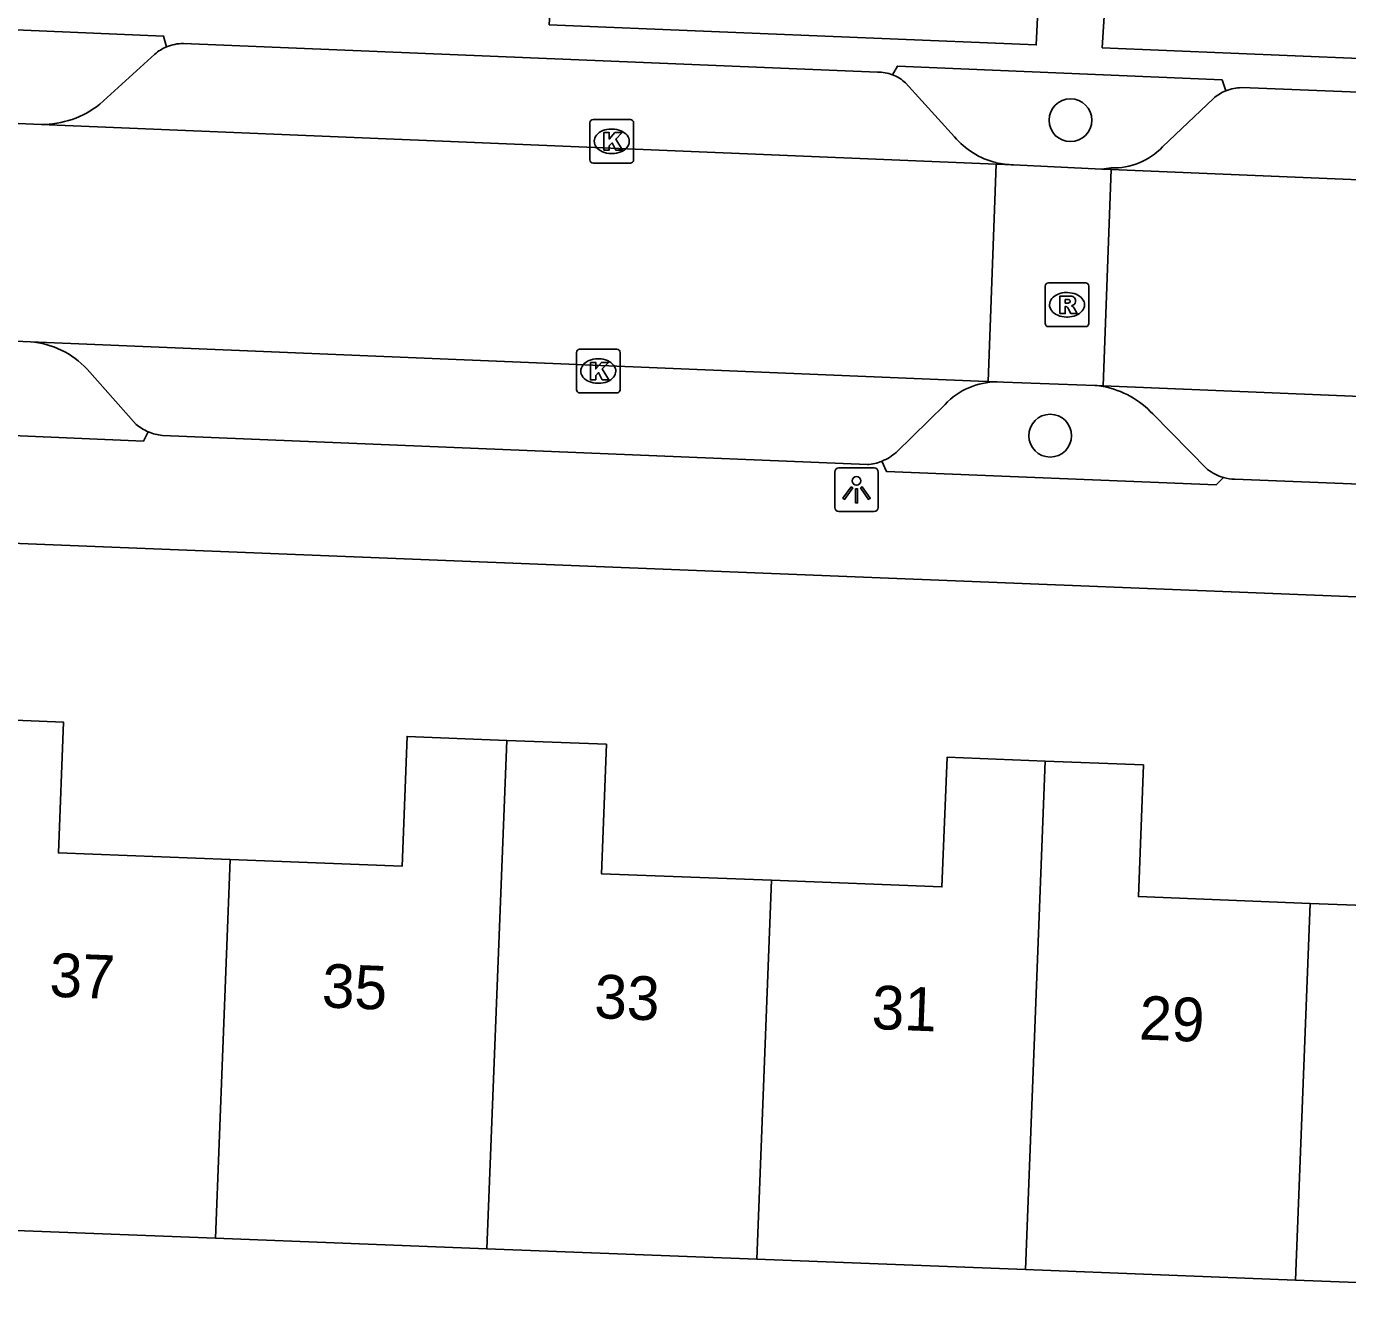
# Model space of a CAD drawing. Extents: x 161355 to 162026, y 386504 to 387459.
# Drawn here: x 161556.51 to 161586.73, y 387199.28 to 387228.21 of the extents above; entities that cross this region are included whole.
import ezdxf

# ---------------------------------------------------------------- set-up
doc = ezdxf.new("R2010")
doc.units = 0
for name, color, linetype in [('IMGEO_Boom', 7, 'Continuous'), ('IMGEO_Kolk', 7, 'Continuous'), ('IMGEO_Lichtpunt', 7, 'Continuous'), ('IMGEO_Pand', 7, 'Continuous'), ('IMGEO_Pand_nummerreeks', 7, 'Continuous'), ('IMGEO_Parkeervlak_open', 7, 'Continuous'), ('IMGEO_Rijbaan_lokaal_open', 7, 'Continuous'), ('IMGEO_Rioolput', 7, 'Continuous'), ('IMGEO_Voetpad_open', 7, 'Continuous')]:
    doc.layers.add(name, color=color, linetype=linetype)

msp = doc.modelspace()

# ---------------------------------------------------------------- linework, layer by layer
at = {"layer": 'IMGEO_Boom'}
for centre in [(161580.392, 387226.062), (161579.931, 387218.844)]:
    msp.add_circle(centre, 0.489, dxfattribs=at)
at = {"layer": 'IMGEO_Kolk'}
for p, q in [((161569.399, 387225.154), (161569.399, 387226.006)), ((161569.474, 387226.08), (161570.326, 387226.08)), ((161570.4, 387226.006), (161570.4, 387225.154)), ((161569.887, 387225.86), (161569.912, 387225.86)), ((161569.91, 387225.3), (161569.885, 387225.3)), ((161570.326, 387225.08), (161569.474, 387225.08)), ((161569.091, 387219.896), (161569.091, 387220.748)), ((161569.166, 387220.822), (161570.018, 387220.822)), ((161570.092, 387220.748), (161570.092, 387219.896)), ((161569.579, 387220.602), (161569.604, 387220.602)), ((161569.602, 387220.042), (161569.577, 387220.042)), ((161570.018, 387219.822), (161569.166, 387219.822))]:
    msp.add_line(p, q, dxfattribs=at)
for points in [[(161569.399, 387225.154), (161569.399, 387226.006)], [(161569.474, 387226.08), (161570.326, 387226.08)], [(161570.4, 387226.006), (161570.4, 387225.154)], [(161569.72, 387225.78), (161569.843, 387225.78), (161569.843, 387225.629), (161569.973, 387225.78), (161570.137, 387225.78), (161569.991, 387225.629), (161570.144, 387225.38), (161569.992, 387225.38), (161569.907, 387225.544), (161569.843, 387225.477), (161569.843, 387225.38), (161569.72, 387225.38), (161569.72, 387225.78)], [(161570.326, 387225.08), (161569.474, 387225.08)], [(161569.091, 387219.896), (161569.091, 387220.748)], [(161569.166, 387220.822), (161570.018, 387220.822)], [(161570.092, 387220.748), (161570.092, 387219.896)], [(161569.412, 387220.522), (161569.535, 387220.522), (161569.535, 387220.371), (161569.665, 387220.522), (161569.829, 387220.522), (161569.683, 387220.371), (161569.836, 387220.122), (161569.684, 387220.122), (161569.599, 387220.286), (161569.535, 387220.219), (161569.535, 387220.122), (161569.412, 387220.122), (161569.412, 387220.522)], [(161570.018, 387219.822), (161569.166, 387219.822)]]:
    msp.add_lwpolyline(points, dxfattribs=at)
for centre, start, end in [((161569.476, 387226.004), 91.552, 178.448), ((161569.476, 387226.004), 91.552, 178.448), ((161570.324, 387226.004), 1.552, 88.448), ((161570.324, 387226.004), 1.552, 88.448), ((161569.476, 387225.156), 181.552, 268.448), ((161569.476, 387225.156), 181.552, 268.448), ((161570.324, 387225.156), 271.552, 358.448), ((161570.324, 387225.156), 271.552, 358.448), ((161569.168, 387220.746), 91.552, 178.448), ((161569.168, 387220.746), 91.552, 178.448), ((161570.016, 387220.746), 1.552, 88.448), ((161570.016, 387220.746), 1.552, 88.448), ((161569.168, 387219.898), 181.552, 268.448), ((161569.168, 387219.898), 181.552, 268.448), ((161570.016, 387219.898), 271.552, 358.448), ((161570.016, 387219.898), 271.552, 358.448)]:
    msp.add_arc(centre, 0.0765, start, end, dxfattribs=at)
for centre, major_axis, ratio, start_param, end_param in [((161569.886, 387225.58), (-0.387, 0.002), 0.722429, 4.712389, 7.853982), ((161569.911, 387225.58), (-0.39, 0.002), 0.717154, 1.570796, 4.712389), ((161569.578, 387220.322), (-0.387, 0.002), 0.722429, 4.712389, 7.853982), ((161569.603, 387220.322), (-0.39, 0.002), 0.717154, 1.570796, 4.712389)]:
    msp.add_ellipse(centre, major_axis=major_axis, ratio=ratio, start_param=start_param, end_param=end_param, dxfattribs=at)
at = {"layer": 'IMGEO_Lichtpunt'}
for p, q in [((161575.903, 387218.106), (161575.095, 387218.106)), ((161575.903, 387218.106), (161575.095, 387218.106)), ((161575.001, 387218.011), (161575.001, 387217.204)), ((161575.001, 387218.011), (161575.001, 387217.204)), ((161575.997, 387217.204), (161575.997, 387218.011)), ((161575.997, 387217.204), (161575.997, 387218.011)), ((161575.095, 387217.11), (161575.903, 387217.11)), ((161575.095, 387217.11), (161575.903, 387217.11))]:
    msp.add_line(p, q, dxfattribs=at)
for points in [[(161575.375, 387217.675), (161575.414, 387217.647), (161575.226, 387217.385), (161575.188, 387217.412), (161575.375, 387217.675)], [(161575.477, 387217.627), (161575.524, 387217.627), (161575.524, 387217.305), (161575.477, 387217.305), (161575.477, 387217.627)], [(161575.587, 387217.647), (161575.625, 387217.674), (161575.812, 387217.412), (161575.773, 387217.384), (161575.587, 387217.647)]]:
    msp.add_lwpolyline(points, dxfattribs=at)
msp.add_circle((161575.5, 387217.809), 0.0994, dxfattribs=at)
for centre, start, end in [((161575.095, 387218.011), 90, 180), ((161575.095, 387218.011), 90, 180), ((161575.903, 387218.011), 0, 90), ((161575.903, 387218.011), 0, 90), ((161575.095, 387217.204), 180, 270), ((161575.095, 387217.204), 180, 270), ((161575.903, 387217.204), 270, 0), ((161575.903, 387217.204), 270, 360)]:
    msp.add_arc(centre, 0.0946, start, end, dxfattribs=at)
at = {"layer": 'IMGEO_Pand'}
for points in [[(161555.125, 387212.379), (161557.357, 387212.292), (161557.241, 387209.297), (161561.172, 387209.144)], [(161561.172, 387209.144), (161565.103, 387208.992), (161565.218, 387211.961), (161567.498, 387211.872)], [(161567.042, 387200.241), (161567.498, 387211.872)], [(161567.498, 387211.872), (161569.777, 387211.784), (161569.662, 387208.821), (161573.558, 387208.67)], [(161573.558, 387208.67), (161577.454, 387208.518), (161577.569, 387211.484), (161579.818, 387211.397)], [(161579.818, 387211.397), (161579.361, 387199.763)], [(161579.818, 387211.397), (161582.063, 387211.31), (161581.946, 387208.296), (161585.88, 387208.143)], [(161585.88, 387208.143), (161589.814, 387207.991), (161589.93, 387210.974), (161592.2, 387210.886)], [(161561.172, 387209.144), (161560.833, 387200.482)], [(161573.218, 387200.001), (161573.558, 387208.67)], [(161585.542, 387199.523), (161585.88, 387208.143)], [(161554.667, 387200.721), (161560.833, 387200.482)], [(161560.833, 387200.482), (161567.042, 387200.241)], [(161573.218, 387200.001), (161567.042, 387200.241)], [(161579.361, 387199.763), (161573.218, 387200.001)], [(161579.361, 387199.763), (161585.542, 387199.523)], [(161591.744, 387199.282), (161585.542, 387199.523)]]:
    msp.add_lwpolyline(points, dxfattribs=at)
at = {"layer": 'IMGEO_Parkeervlak_open'}
for points in [[(161559.446, 387227.575), (161558.189, 387226.426)], [(161577.74, 387225.684), (161576.62, 387226.914)], [(161583.663, 387226.562), (161582.501, 387225.45)], [(161581.322, 387224.972), (161581.107, 387224.942)], [(161557.9, 387220.367), (161559.02, 387219.099)], [(161576.407, 387218.462), (161577.524, 387219.56)], [(161582.278, 387219.34), (161583.531, 387218.073)]]:
    msp.add_lwpolyline(points, dxfattribs=at)
for centre, radius, start, end in [((161560.086, 387226.832), 0.98, 112.0404, 130.7505), ((161575.999, 387226.256), 0.905, 46.6409, 69.2111), ((161584.343, 387225.756), 1.055, 111.8289, 130.1572), ((161556.861, 387228.107), 2.142, 269.6185, 308.2985), ((161579.124, 387226.844), 1.805, 219.9726, 256.1359), ((161581.368, 387226.552), 1.581, 268.3377, 315.8003), ((161579.274, 387228.005), 2.972, 258.6846, 266.428), ((161556.442, 387219.003), 1.996, 43.0974, 85.4429), ((161578.72, 387218.429), 1.646, 90.1756, 136.5926), ((161580.808, 387218.321), 1.681, 78.4532, 84.7609), ((161580.755, 387217.929), 2.076, 42.8222, 79.1803), ((161559.759, 387220.014), 1.176, 231.0801, 246.9318), ((161575.647, 387219.328), 1.152, 292.1899, 311.2805), ((161584.171, 387218.871), 1.023, 231.2933, 254.1884)]:
    msp.add_arc(centre, radius, start, end, dxfattribs=at)
at = {"layer": 'IMGEO_Rijbaan_lokaal_open'}
for points in [[(161554.732, 387226.054), (161556.847, 387225.965)], [(161556.847, 387225.965), (161578.69, 387225.056)], [(161578.69, 387225.056), (161578.512, 387220.084)], [(161578.69, 387225.056), (161579.089, 387225.039)], [(161581.107, 387224.942), (161579.089, 387225.039)], [(161581.107, 387224.942), (161581.321, 387224.933)], [(161581.145, 387219.987), (161581.321, 387224.933)], [(161581.321, 387224.933), (161603.641, 387224.004)], [(161556.601, 387220.993), (161554.463, 387221.084)], [(161578.512, 387220.084), (161578.471, 387220.085), (161556.601, 387220.993)], [(161578.715, 387220.075), (161578.512, 387220.084)], [(161578.715, 387220.075), (161578.863, 387220.069), (161580.962, 387219.995)], [(161581.145, 387219.987), (161580.962, 387219.995)], [(161603.228, 387219.072), (161581.145, 387219.987)]]:
    msp.add_lwpolyline(points, dxfattribs=at)
at = {"layer": 'IMGEO_Rioolput'}
for p, q in [((161579.814, 387221.413), (161579.814, 387222.265)), ((161579.889, 387222.339), (161580.741, 387222.339)), ((161580.815, 387222.265), (161580.815, 387221.413)), ((161580.302, 387222.119), (161580.327, 387222.119)), ((161580.325, 387221.559), (161580.3, 387221.559)), ((161580.741, 387221.339), (161579.889, 387221.339))]:
    msp.add_line(p, q, dxfattribs=at)
for points in [[(161579.814, 387221.413), (161579.814, 387222.265)], [(161579.889, 387222.339), (161580.741, 387222.339)], [(161580.815, 387222.265), (161580.815, 387221.413)], [(161580.403, 387222.037), (161580.151, 387222.039), (161580.151, 387221.639)], [(161580.329, 387221.958), (161580.275, 387221.958), (161580.275, 387221.877)], [(161580.151, 387221.639), (161580.275, 387221.639), (161580.275, 387221.801), (161580.286, 387221.801)], [(161580.275, 387221.877), (161580.327, 387221.877)], [(161580.333, 387221.772), (161580.404, 387221.639), (161580.544, 387221.639), (161580.479, 387221.765)], [(161580.741, 387221.339), (161579.889, 387221.339)]]:
    msp.add_lwpolyline(points, dxfattribs=at)
for centre, radius, start, end in [((161579.891, 387222.263), 0.0765, 91.552, 178.448), ((161579.891, 387222.263), 0.0765, 91.552, 178.448), ((161580.739, 387222.263), 0.0765, 1.552, 88.448), ((161580.739, 387222.263), 0.0765, 1.552, 88.448), ((161580.335, 387221.862), 0.0964, 77.0061, 93.1865), ((161580.349, 387221.919), 0.0378, 276.6634, 79.6772), ((161580.402, 387221.927), 0.109, 350.3612, 89.416), ((161580.285, 387221.748), 0.0533, 26.0293, 88.6989), ((161580.311, 387222.066), 0.19, 274.7715, 282.9687), ((161580.4, 387221.927), 0.112, 277.5842, 350.9817), ((161580.384, 387221.712), 0.108, 29.5134, 73.7905), ((161579.891, 387221.415), 0.0765, 181.552, 268.448), ((161579.891, 387221.415), 0.0765, 181.552, 268.448), ((161580.739, 387221.415), 0.0765, 271.552, 358.448), ((161580.739, 387221.415), 0.0765, 271.552, 358.448)]:
    msp.add_arc(centre, radius, start, end, dxfattribs=at)
for centre, major_axis, ratio, start_param, end_param in [((161580.301, 387221.839), (-0.387, 0.002), 0.722429, 4.712389, 7.853982), ((161580.326, 387221.839), (-0.39, 0.002), 0.717154, 1.570796, 4.712389)]:
    msp.add_ellipse(centre, major_axis=major_axis, ratio=ratio, start_param=start_param, end_param=end_param, dxfattribs=at)
at = {"layer": 'IMGEO_Voetpad_open'}
for points in [[(161568.471, 387228.245), (161568.563, 387229.805), (161579.686, 387229.343), (161579.61, 387227.784), (161568.471, 387228.245)], [(161581.122, 387227.718), (161581.214, 387229.288), (161591.499, 387228.859), (161591.416, 387227.293), (161581.122, 387227.718)], [(161551.991, 387228.133), (161552.169, 387228.306), (161559.647, 387227.988), (161559.718, 387227.741)], [(161560.101, 387227.818), (161575.979, 387227.161)], [(161576.32, 387227.102), (161576.435, 387227.3), (161583.863, 387226.985), (161583.951, 387226.735)], [(161584.31, 387226.81), (161600.499, 387226.164)], [(161559.298, 387218.932), (161559.186, 387218.721), (161551.777, 387219.04), (161551.697, 387219.261)], [(161559.622, 387218.848), (161575.748, 387218.181)], [(161583.892, 387217.887), (161583.727, 387217.72), (161576.184, 387218.025), (161576.082, 387218.261)], [(161584.153, 387217.849), (161599.979, 387217.212)], [(161611.197, 387214.187), (161529.603, 387217.441)]]:
    msp.add_lwpolyline(points, dxfattribs=at)
for centre, radius, start, end in [((161560.107, 387226.795), 1.023, 90.3566, 112.3783), ((161575.998, 387226.256), 0.906, 69.1684, 91.1993), ((161584.345, 387225.744), 1.066, 91.8963, 111.704), ((161559.743, 387219.98), 1.138, 247.0117, 263.9193), ((161575.659, 387219.289), 1.112, 274.585, 292.3546), ((161584.159, 387218.807), 0.958, 253.8023, 269.6303)]:
    msp.add_arc(centre, radius, start, end, dxfattribs=at)

# ---------------------------------------------------------------- texts
at = {"layer": 'IMGEO_Pand_nummerreeks'}
for s, p in [('37', (161557.027, 387206.009)), ('35', (161563.258, 387205.764)), ('33', (161569.489, 387205.519)), ('31', (161575.833, 387205.27)), ('29', (161581.951, 387205.03))]:
    msp.add_text(s, height=1, rotation=357.7506, dxfattribs=at).set_placement(p)

doc.saveas('drawing.dxf')
